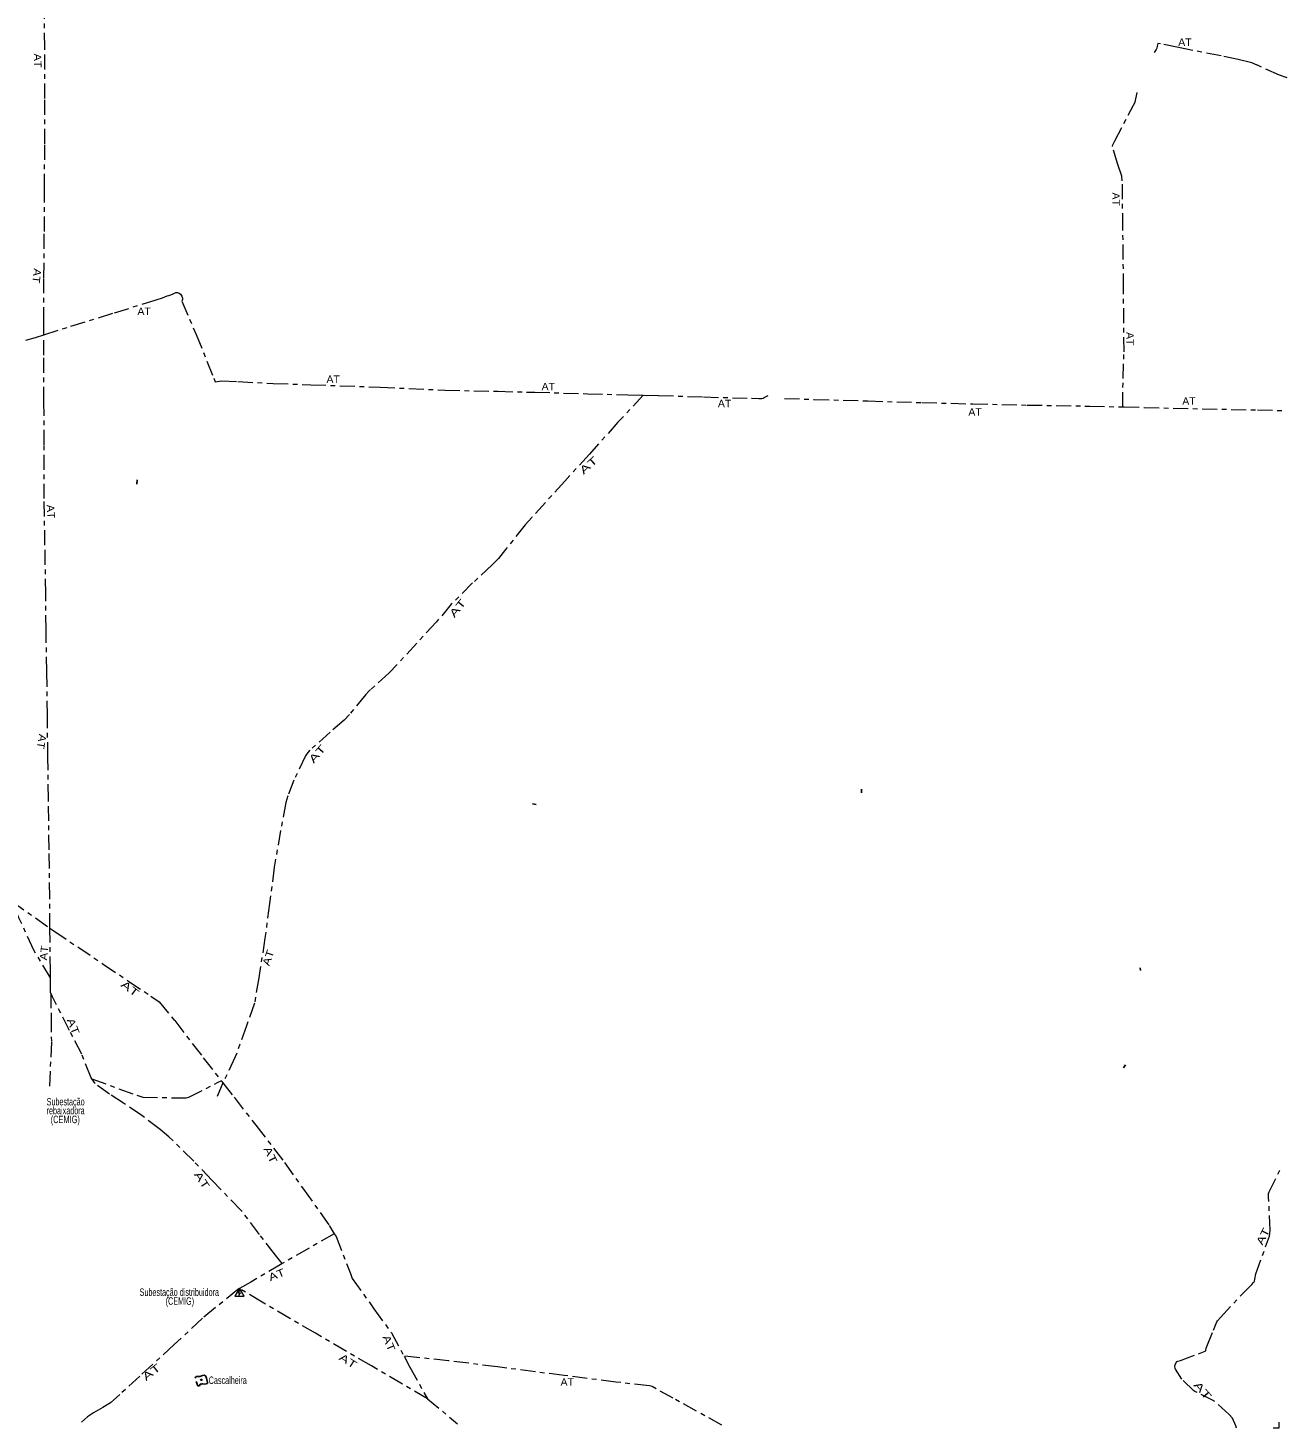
# Model space of a CAD drawing. Extents: x 552.5 to 605.3, y 7843.5 to 7899.1.
# Drawn here: x 578.1 to 605.11, y 7843.52 to 7873.54 of the extents above; entities that cross this region are included whole.
import ezdxf
from ezdxf.enums import TextEntityAlignment as Align

# ---------------------------------------------------------------- set-up
doc = ezdxf.new("R2010")
doc.units = 0
doc.header["$LTSCALE"] = 0.064
doc.header["$PDMODE"] = 32
doc.header["$PDSIZE"] = 0.032
doc.linetypes.add('DOT_DASHED', pattern=[7.7, 5, -1.2, 0.3, -1.2])
doc.linetypes.add('SHORT_DASHED', pattern=[2.7, 1.5, -1.2])
for name, color, linetype, lineweight in [('2', 7, 'Continuous', 13), ('24', 7, 'Continuous', 25), ('48', 7, 'Continuous', 13), ('56', 7, 'DOT_DASHED', 13), ('63', 7, 'Continuous', 13)]:
    doc.layers.add(name, color=color, linetype=linetype, lineweight=lineweight)
doc.layers.add('61', color=7, linetype='Continuous')

msp = doc.modelspace()

# ---------------------------------------------------------------- hatches: boundary and pattern name
at = {"layer": '2'}
msp.add_hatch(color=256, dxfattribs=at).paths.add_polyline_path([(582.6247, 7846.4674), (582.6507, 7846.4824), (582.6507, 7846.4524)])

# ---------------------------------------------------------------- linework, layer by layer
for p, q in [((582.6147, 7846.4204), (582.6377, 7846.4604)), ((582.6147, 7846.4204), (582.6647, 7846.4204)), ((582.6297, 7846.3594), (582.6647, 7846.4204))]:
    msp.add_line(p, q, dxfattribs=at)
for points in [[(582.7407, 7846.3464), (582.6407, 7846.5194), (582.5407, 7846.3464)], [(582.6247, 7846.4674), (582.6507, 7846.4824), (582.6507, 7846.4524)]]:
    msp.add_lwpolyline(points, close=True, dxfattribs=at)
at = {"layer": '24'}
for p, q in [((580.4364, 7863.7531), (580.4469, 7863.8517)), ((595.9831, 7857.2155), (595.9786, 7857.1377)), ((588.9235, 7856.9046), (589.0044, 7856.8852)), ((601.9589, 7853.3889), (601.9687, 7853.3276))]:
    msp.add_line(p, q, dxfattribs=at)
msp.add_lwpolyline([(601.5988, 7851.2387), (601.6189, 7851.2663), (601.6467, 7851.3045)], dxfattribs=at)
at = {"layer": '48', "linetype": 'SHORT_DASHED', "lineweight": 25}
msp.add_lwpolyline([(581.7499, 7844.4265), (581.6904, 7844.5856), (581.695, 7844.6087), (581.7135, 7844.6215), (581.7424, 7844.6238), (581.7655, 7844.6215), (581.791, 7844.6249), (581.8118, 7844.633), (581.8453, 7844.6457), (581.8869, 7844.6527), (581.8973, 7844.6492), (581.9112, 7844.6365), (581.9354, 7844.5856), (581.9562, 7844.4955), (581.9551, 7844.477), (581.9226, 7844.4638), (581.8869, 7844.462), (581.858, 7844.4654), (581.8418, 7844.4654), (581.8175, 7844.4631), (581.799, 7844.4573), (581.7874, 7844.4465), (581.7799, 7844.4272)], close=True, dxfattribs=at)
at = {"layer": '48'}
msp.add_point((581.8198, 7844.5521), dxfattribs=at)
at = {"layer": '56'}
for p, q in [((584.6738, 7847.6835), (583.5557, 7847.0434)), ((586.6699, 7844.1465), (587.315, 7843.6086))]:
    msp.add_line(p, q, dxfattribs=at)
for points in [[(578.4476, 7866.9591), (578.4476, 7867.2281), (578.4457, 7868.1818), (578.4552, 7869.1732), (578.457, 7870.0894), (578.4664, 7871.0545), (578.4646, 7872.0271), (578.4627, 7873.1125), (578.457, 7874.0776), (578.4608, 7874.9824), (578.3968, 7875.5581), (578.3122, 7876.3708), (578.2841, 7876.6789)], [(605.1088, 7872.4652), (604.9484, 7872.5255), (604.4688, 7872.7404), (604.3511, 7872.786), (604.0642, 7872.861), (603.6949, 7872.936), (602.7783, 7873.1155), (602.3956, 7873.1976), (602.3351, 7873.2045), (602.3234, 7873.1492), (602.3152, 7873.1027), (602.3029, 7873.0713), (602.2596, 7873.012)], [(601.5876, 7865.4113), (601.5917, 7866.0189), (601.6135, 7866.5897), (601.6026, 7867.953), (601.5893, 7869.2461), (601.5759, 7870.256), (601.5652, 7870.3575), (601.4771, 7870.6113), (601.3622, 7870.9987), (601.3702, 7871.0281), (601.4183, 7871.1162), (601.8137, 7871.883), (601.8511, 7871.9471), (601.8939, 7872.1555)], [(578.4476, 7866.9591), (579.0221, 7867.1432), (579.9587, 7867.4301), (580.8515, 7867.7086), (580.9901, 7867.754), (581.0927, 7867.79), (581.127, 7867.7974), (581.1701, 7867.8123), (581.2207, 7867.8391), (581.2474, 7867.8525), (581.2757, 7867.8614), (581.3114, 7867.8629), (581.3278, 7867.8584), (581.3501, 7867.848), (581.3769, 7867.8302), (581.3917, 7867.8093), (581.4051, 7867.7855), (581.4185, 7867.7439), (581.4215, 7867.7141), (581.4141, 7867.6933), (581.4051, 7867.6762), (581.7108, 7866.9668), (582.0885, 7866.026), (582.116, 7865.9527), (582.2579, 7865.9733), (582.6058, 7865.955), (583.3635, 7865.9161), (584.1738, 7865.8886), (585.6548, 7865.836), (587.0465, 7865.7719), (588.1805, 7865.746), (588.974, 7865.7273), (590.1054, 7865.6939), (590.9682, 7865.6721), (591.2993, 7865.6641)], [(578.0601, 7866.8395), (578.266, 7866.9036), (578.4476, 7866.9591)], [(578.5739, 7854.2377), (578.5718, 7854.8967), (578.5567, 7855.9144), (578.5417, 7857.0018), (578.5304, 7857.9048), (578.521, 7858.7908), (578.5078, 7859.7352), (578.4928, 7860.6288), (578.4853, 7861.4057), (578.4683, 7862.446), (578.4495, 7863.4449), (578.4495, 7864.6), (578.4476, 7865.5218), (578.4476, 7866.5226), (578.4476, 7866.9591)], [(591.2993, 7865.6641), (590.759, 7865.0824), (590.1461, 7864.4012), (589.6203, 7863.8232), (588.913, 7863.0432), (588.7677, 7862.8863), (588.348, 7862.3533), (588.194, 7862.1587), (588.059, 7862.0265), (587.6421, 7861.6372), (587.1846, 7861.1797), (586.865, 7860.8035), (585.8541, 7859.7084), (585.4518, 7859.3497), (585.4141, 7859.3177), (585.3516, 7859.248), (585.0016, 7858.8195), (584.8854, 7858.6961), (584.5891, 7858.4361), (584.1504, 7858.0497), (584.104, 7858.0003), (584.0589, 7857.9321), (583.8048, 7857.4092), (583.6769, 7857.0751), (583.6363, 7856.9313), (583.523, 7856.3286), (583.3864, 7855.5443), (583.2862, 7854.7672), (583.1875, 7854.025), (583.0553, 7853.1695), (582.9609, 7852.6248), (582.7895, 7852.1412), (582.5513, 7851.4745), (582.287, 7850.9181), (582.1362, 7850.5737)], [(591.2993, 7865.6641), (591.6305, 7865.6562), (592.592, 7865.6257), (593.6217, 7865.5957), (593.6284, 7865.597), (593.7825, 7865.5955), (593.847, 7865.5955), (593.8729, 7865.6018), (593.8973, 7865.6159), (593.9264, 7865.6293), (593.9523, 7865.6419), (593.9798, 7865.6552)], [(594.332, 7865.5922), (594.9697, 7865.5734), (596.1171, 7865.54), (597.2776, 7865.5036), (598.3727, 7865.4775), (599.5361, 7865.4514), (600.8753, 7865.4281), (601.5876, 7865.4113)], [(601.5876, 7865.4113), (601.6183, 7865.4106), (602.046, 7865.4005), (603.2922, 7865.37), (604.4744, 7865.3482), (605.0665, 7865.3337)], [(578.5884, 7853.1697), (578.2294, 7853.7661), (577.9115, 7854.4584), (577.7575, 7854.8151), (578.5739, 7854.2377)], [(578.5739, 7854.2377), (578.6563, 7854.1795), (579.7176, 7853.4665), (580.249, 7853.1093), (580.742, 7852.7787), (580.9162, 7852.6561), (581.2512, 7852.2561), (581.8638, 7851.459), (582.2502, 7850.965)], [(578.5884, 7853.1697), (578.5875, 7853.3121), (578.5739, 7854.2377)], [(578.5937, 7852.8418), (578.5903, 7852.8492), (578.5884, 7853.1697)], [(578.5937, 7852.8418), (578.6, 7852.3265), (578.6056, 7851.7899), (578.5635, 7850.8367)], [(579.4729, 7851.0053), (579.4578, 7851.0267), (579.2562, 7851.5355), (578.9962, 7852.0415), (578.6278, 7852.7672), (578.5937, 7852.8418)], [(583.5557, 7847.0434), (583.41, 7847.2274), (583.0736, 7847.6681), (582.6788, 7848.1839), (582.0546, 7848.8289), (581.6598, 7849.2376), (581.1287, 7849.7659), (580.9397, 7849.9216), (580.5463, 7850.2218), (580.1556, 7850.486), (579.8553, 7850.6792), (579.5453, 7850.903), (579.4729, 7851.0053)], [(579.4729, 7851.0053), (580.4394, 7850.6554), (580.5647, 7850.6137), (581.4983, 7850.5953), (581.5534, 7850.612), (582.1831, 7850.931), (582.2502, 7850.965), (582.287, 7850.9181)], [(582.287, 7850.9181), (582.5266, 7850.6118), (582.993, 7850.0095), (583.6085, 7849.2124), (584.0115, 7848.6427), (584.5621, 7847.8648), (584.6738, 7847.6835)], [(604.025, 7843.5198), (604.0144, 7843.5694), (603.9369, 7843.7276), (603.8669, 7843.8104), (603.5538, 7844.0916), (603.1303, 7844.3039), (603.1133, 7844.3145), (602.8522, 7844.5661), (602.7195, 7844.7805), (602.7078, 7844.8049), (602.7025, 7844.8335), (602.7089, 7844.8824), (602.7492, 7844.945), (602.7641, 7844.9535), (602.8256, 7844.9683), (603.2109, 7845.1106), (603.316, 7845.1519), (603.3553, 7845.1689), (603.3701, 7845.1806), (603.3776, 7845.2305), (603.3924, 7845.2666), (603.5325, 7845.62), (603.5877, 7845.7601), (603.6026, 7845.7941), (603.6185, 7845.8195), (603.6811, 7845.8896), (604.1375, 7846.3789), (604.353, 7846.5997), (604.3901, 7846.6379), (604.4018, 7846.6506), (604.4124, 7846.6665), (604.4166, 7846.71), (604.4432, 7846.8225), (604.7298, 7847.6313), (604.7446, 7847.7587), (604.7149, 7848.4698), (604.7149, 7848.5462), (604.7255, 7848.5823), (604.9723, 7849.0833)], [(584.6738, 7847.6835), (584.7112, 7847.6227), (585.0226, 7846.8301), (585.0595, 7846.7282), (585.523, 7846.0773), (585.8979, 7845.5592), (586.1695, 7845.0593)], [(583.5557, 7847.0434), (583.547, 7847.0384), (582.8817, 7846.6478), (582.6386, 7846.5083)], [(582.6386, 7846.5083), (582.6079, 7846.4907), (581.8447, 7845.872), (581.2427, 7845.3076), (580.5032, 7844.632), (580.0764, 7844.2386), (579.8734, 7844.0607), (579.7108, 7843.962), (579.5092, 7843.8452), (579.3785, 7843.7562), (579.252, 7843.6458)], [(586.6699, 7844.1465), (585.4713, 7844.8492), (584.2698, 7845.5503), (583.1288, 7846.2145), (582.6386, 7846.5083)], [(592.988, 7843.5802), (591.945, 7844.1571), (591.4938, 7844.4069), (591.4326, 7844.4214), (590.7155, 7844.5052), (589.602, 7844.6454), (588.1727, 7844.8291), (587.1253, 7844.9628), (586.1695, 7845.0593)], [(586.1695, 7845.0593), (586.2965, 7844.8255), (586.6699, 7844.1465)]]:
    msp.add_lwpolyline(points, dxfattribs=at)
at = {"layer": '63'}
msp.add_lwpolyline([(604.8143, 7843.5267), (604.9375, 7843.5267), (604.9375, 7843.6481)], dxfattribs=at)

# ---------------------------------------------------------------- texts
at = {"layer": '61', "width": 1.05}
for p in [(602.91975, 7873.1523), (580.59585, 7867.3813), (584.65035, 7865.9263), (589.26415, 7865.7678), (593.04545, 7865.4059), (603.00575, 7865.4575), (598.41815, 7865.2234), (589.67095, 7844.426)]:
    msp.add_text('AT', height=0.16, dxfattribs=at).set_placement(p, align=Align.CENTER)
at = {"layer": '61'}
for rotation, width, p in [(271.219, 1.1, (578.23291, 7872.83595)), (270, 1.05, (601.3626, 7869.86535)), (263.66, 1.15, (578.21379, 7868.23198)), (270, 1.05, (601.6609, 7866.87275)), (41.987, 1.6, (590.18203, 7864.09986)), (274.399, 1.1, (578.51524, 7863.16094)), (51.34, 1.55, (587.3822, 7861.04702)), (260.538, 1.15, (578.31789, 7858.25175)), (49.399, 1.55, (584.3693, 7857.91959)), (84.289, 1.15, (578.52905, 7853.69679)), (71.565, 1.25, (583.33383, 7853.5752)), (323.13, 1.5, (580.24545, 7852.87509)), (291.801, 1.3, (579.00086, 7852.10306)), (296.565, 1.35, (583.23401, 7849.33728)), (303.69, 1.45, (581.76732, 7848.78908)), (63.435, 1.35, (604.66469, 7847.59187)), (21.801, 1.3, (583.46774, 7846.73176)), (292.38, 1.3, (585.77356, 7845.30756)), (327.679, 1.45, (584.92638, 7844.88821)), (38.29, 1.55, (580.80253, 7844.65325)), (311.186, 1.6, (603.23757, 7844.26938))]:
    msp.add_text('AT', height=0.16, rotation=rotation, dxfattribs=dict(at, width=width)).set_placement(p, align=Align.CENTER)
for s, width, p in [('Subestação', 0.7, (578.5035, 7850.4359)), ('rebaixadora', 0.7, (578.5035, 7850.2459)), ('  (CEMIG)', 0.65, (578.5035, 7850.0559)), ('Subestação distribuidora', 0.7, (580.4987, 7846.3517)), ('             (CEMIG)', 0.7, (580.4987, 7846.1617)), ('Cascalheira', 0.7, (581.9804, 7844.4634))]:
    msp.add_text(s, height=0.16, dxfattribs=dict(at, width=width)).set_placement(p)

doc.saveas('drawing.dxf')
